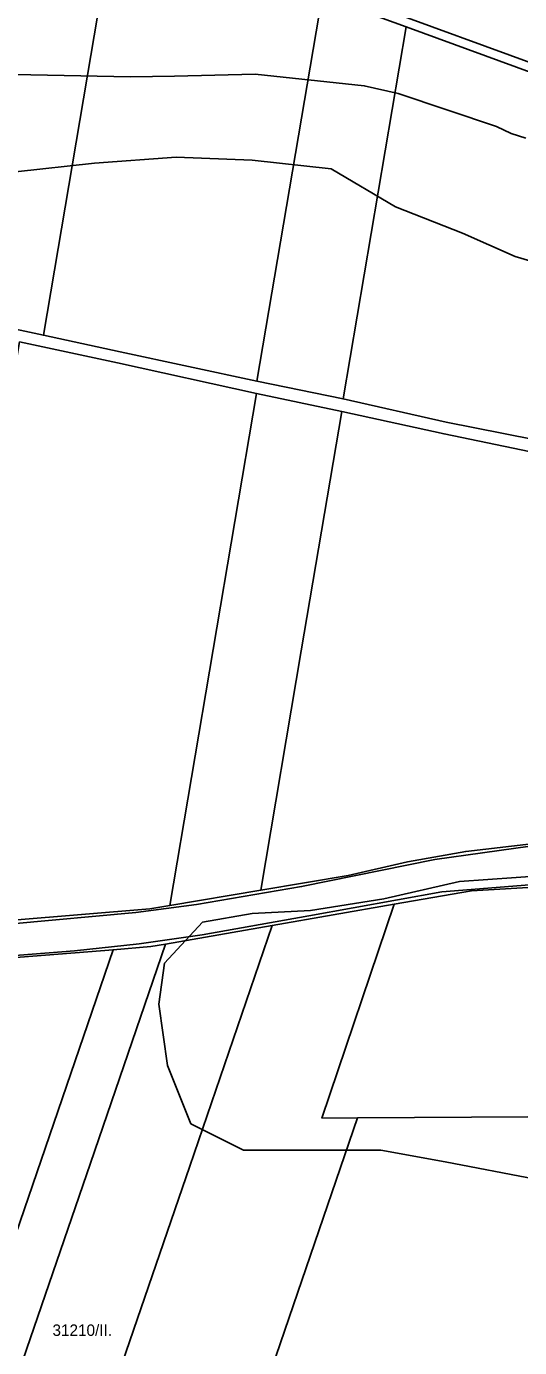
# Model space of a CAD drawing. Extents: x -545779 to -541342, y -1153413 to -1149956.
# Drawn here: x -544701 to -544486, y -1151643 to -1151066 of the extents above; entities that cross this region are included whole.
import ezdxf

# ---------------------------------------------------------------- set-up
doc = ezdxf.new("R2010")
doc.units = 0
for name, color, linetype in [('95560013', 7, 'Continuous'), ('95640013', 7, 'Continuous'), ('95660013', 7, 'Continuous')]:
    doc.layers.add(name, color=color, linetype=linetype)

msp = doc.modelspace()

# ---------------------------------------------------------------- linework, layer by layer
at = {"layer": '95560013'}
for points in [[(-544772.07, -1151183.88), (-544751.2, -1151060.43), (-544702.36, -1151037.75), (-544677.65, -1151031.52), (-544665.31, -1151031.77), (-544693.86, -1151200.59), (-544755.74, -1151187.33)], [(-544693.86, -1151200.59), (-544665.31, -1151031.77), (-544625.98, -1151032.55), (-544572.2, -1151052.38), (-544600.65, -1151220.62), (-544660.38, -1151207.76)], [(-544562.96, -1151228.39), (-544600.65, -1151220.62), (-544572.2, -1151052.38), (-544535.48, -1151065.83)], [(-544517.96, -1151238.54), (-544562.96, -1151228.39), (-544535.48, -1151065.83), (-544392.55, -1151118.14), (-544416.31, -1151258.67)], [(-544600.85, -1151225.95), (-544619.76, -1151337.8), (-544638.67, -1151449.66), (-544647.37, -1151451.12), (-544707.14, -1151456.12), (-544747.7, -1151460.17), (-544726, -1151331.82), (-544704.3, -1151203.48), (-544661.5, -1151212.63)], [(-544638.67, -1151449.66), (-544619.76, -1151337.8), (-544600.85, -1151225.95), (-544563.58, -1151233.89), (-544581.26, -1151338.43), (-544598.93, -1151442.97)], [(-544534.87, -1151430.66), (-544560.82, -1151436.56), (-544598.93, -1151442.97), (-544581.26, -1151338.43), (-544563.58, -1151233.89), (-544518.88, -1151243.65), (-544406.01, -1151267.06), (-544432.64, -1151424.59), (-544448.69, -1151423.1), (-544480.64, -1151422.82), (-544509.45, -1151426.08)], [(-544572.23, -1151542.64), (-544540.71, -1151449.17), (-544506.92, -1151443.28), (-544447.61, -1151439.82), (-544480.22, -1151536.5), (-544482.08, -1151542.04), (-544556.71, -1151542.54)], [(-544665.98, -1151668.72), (-544629.97, -1151563.59), (-544593.95, -1151458.46), (-544540.71, -1151449.17), (-544572.23, -1151542.64), (-544556.71, -1151542.54), (-544605.38, -1151684.64)], [(-544665.98, -1151668.72), (-544706.17, -1151658.17), (-544673.36, -1151562.38), (-544640.54, -1151466.58), (-544593.95, -1151458.46), (-544629.97, -1151563.59)], [(-544733.67, -1151474.7), (-544663.43, -1151469.03), (-544726.4, -1151652.86), (-544789.06, -1151636.4)], [(-544646.97, -1151467.7), (-544640.54, -1151466.58), (-544673.36, -1151562.38), (-544706.17, -1151658.17), (-544726.4, -1151652.86), (-544663.43, -1151469.03)], [(-544455.29, -1151722.05), (-544457.82, -1151723.4), (-544605.38, -1151684.64), (-544556.71, -1151542.54), (-544482.08, -1151542.04), (-544385.47, -1151546.37), (-544402.51, -1151579.84), (-544425.47, -1151635.75)]]:
    msp.add_lwpolyline(points, close=True, dxfattribs=at)
at = {"layer": '95640013'}
for points in [[(-544703.7, -1151033.96), (-544678.11, -1151027.51), (-544625.23, -1151028.57), (-544568.77, -1151049.38), (-544456.22, -1151090.58), (-544343.68, -1151131.77), (-544340.09, -1151133.08), (-544340.12, -1151136.85), (-544340.12, -1151137.33), (-544392.55, -1151118.14), (-544535.48, -1151065.83), (-544572.2, -1151052.38), (-544625.98, -1151032.55), (-544665.31, -1151031.77), (-544677.65, -1151031.52), (-544702.36, -1151037.75)], [(-544370.9, -1151057.68), (-544373.75, -1151067.46), (-544373.71, -1151080.64), (-544367.47, -1151101.32), (-544363.59, -1151120.98), (-544343.68, -1151131.77), (-544456.22, -1151090.58), (-544568.77, -1151049.38)], [(-544755.74, -1151187.33), (-544693.86, -1151200.59), (-544660.38, -1151207.76), (-544600.65, -1151220.62), (-544562.96, -1151228.39), (-544517.96, -1151238.54), (-544416.31, -1151258.67)], [(-544406.01, -1151267.06), (-544518.88, -1151243.65), (-544563.58, -1151233.89), (-544600.85, -1151225.95), (-544661.5, -1151212.63), (-544704.3, -1151203.48)], [(-544707.14, -1151456.12), (-544647.37, -1151451.12), (-544638.67, -1151449.66), (-544598.93, -1151442.97), (-544560.82, -1151436.56), (-544534.87, -1151430.66), (-544509.45, -1151426.08), (-544480.64, -1151422.82), (-544448.69, -1151423.1), (-544432.64, -1151424.59), (-544454.9, -1151423.44), (-544481.23, -1151423.83), (-544522.9, -1151429.64), (-544581.14, -1151441.43), (-544627.05, -1151449.27), (-544653.47, -1151452.86), (-544707.54, -1151457.79)], [(-544707.54, -1151457.79), (-544653.47, -1151452.86), (-544627.05, -1151449.27), (-544581.14, -1151441.43), (-544522.9, -1151429.64), (-544481.23, -1151423.83)], [(-544456.12, -1151438.64), (-544519.82, -1151443.71), (-544577.97, -1151454.24), (-544624.55, -1151462.6), (-544652.11, -1151466.54), (-544680.32, -1151469.51), (-544735.88, -1151473.84)], [(-544735.88, -1151473.84), (-544680.32, -1151469.51), (-544652.11, -1151466.54), (-544624.55, -1151462.6), (-544577.97, -1151454.24), (-544519.82, -1151443.71), (-544456.12, -1151438.64), (-544415.66, -1151439.36), (-544447.61, -1151439.82), (-544506.92, -1151443.28), (-544540.71, -1151449.17), (-544593.95, -1151458.46), (-544640.54, -1151466.58), (-544646.97, -1151467.7), (-544663.43, -1151469.03), (-544733.67, -1151474.7)]]:
    msp.add_lwpolyline(points, dxfattribs=at)
at = {"layer": '95660013'}
for points in [[(-544483.213, -1151114.504), (-544489.59, -1151112.378), (-544495.967, -1151109.402), (-544538.903, -1151094.949), (-544553.783, -1151091.547), (-544601.395, -1151086.447), (-544636.68, -1151087.296), (-544655.811, -1151087.722), (-544735.732, -1151086.021)], [(-544735.732, -1151086.021), (-544655.811, -1151087.722), (-544636.68, -1151087.296), (-544601.395, -1151086.447), (-544553.783, -1151091.547), (-544538.903, -1151094.949), (-544495.967, -1151109.402), (-544489.59, -1151112.378), (-544483.213, -1151114.504)], [(-544706.035, -1151129.157), (-544671.583, -1151125.329), (-544635.855, -1151122.777), (-544602.68, -1151124.053), (-544568.23, -1151127.881), (-544540.158, -1151144.468), (-544510.811, -1151155.952), (-544487.844, -1151166.16), (-544466.153, -1151172.539)], [(-544466.153, -1151172.539), (-544487.844, -1151166.16), (-544510.811, -1151155.952), (-544540.158, -1151144.468), (-544568.23, -1151127.881), (-544602.68, -1151124.053), (-544635.855, -1151122.777), (-544671.583, -1151125.329), (-544706.035, -1151129.157)], [(-544475.085, -1151436.665), (-544512.088, -1151439.216), (-544545.263, -1151446.872), (-544577.162, -1151451.976), (-544602.68, -1151453.252), (-544624.373, -1151457.08), (-544640.96, -1151474.944), (-544643.511, -1151492.807), (-544639.684, -1151519.602), (-544629.476, -1151545.122), (-544606.509, -1151556.605), (-544586.094, -1151556.605), (-544546.539, -1151556.605), (-544518.467, -1151561.709), (-544478.912, -1151569.365)], [(-544478.912, -1151569.365), (-544518.467, -1151561.709), (-544546.539, -1151556.605), (-544586.094, -1151556.605), (-544606.509, -1151556.605), (-544629.476, -1151545.122), (-544639.684, -1151519.602), (-544643.511, -1151492.807), (-544640.96, -1151474.944), (-544624.373, -1151457.08), (-544602.68, -1151453.252), (-544577.162, -1151451.976), (-544545.263, -1151446.872), (-544512.088, -1151439.216), (-544475.085, -1151436.665)]]:
    msp.add_lwpolyline(points, dxfattribs=at)

# ---------------------------------------------------------------- texts
msp.add_text('31210/II.', height=5, rotation=0, dxfattribs=at).set_placement((-544689.917, -1151637.789))

doc.saveas('drawing.dxf')
